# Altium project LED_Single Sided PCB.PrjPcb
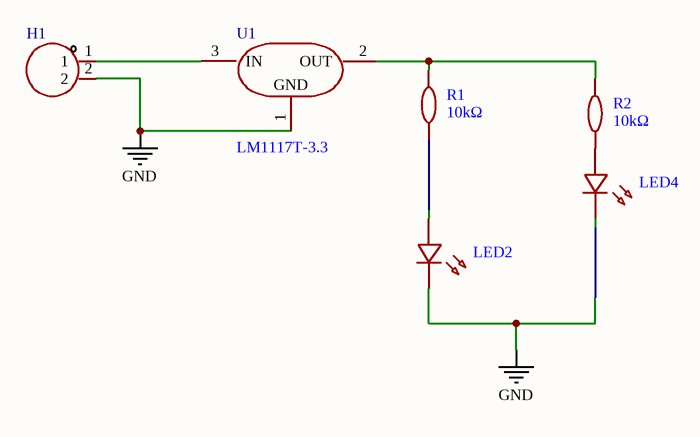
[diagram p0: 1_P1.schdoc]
1 sheet, 6 parts. Net scope: global (net labels, ports and power ports of the same name join across sheets).
Board file: PCB1.pcbdoc

## Sheet 1_P1.schdoc
size 307 x 218 mm; Symbol: Drawing-Symbol_A4; Device: Drawing-Symbol_A4; @Project Name: Single Sided; @Page Count: 1; @Update Date: 2026-02-27; @Create Date: 2026-02-27; @Schematic Name: Schematic1; @Page No: 1; @Page Name: P1; Company: EasyEDA.com; Version: V1.0; Page Size: A4; @Create Time: 07:55:02; @Update Time: 13:25:02; Width: 1170; Height: 825; Region Start: 1; X Region Count: 6; Y Region Count: 4; Blade Width: 10; Title Block Position: 3; @Board Name: Board1; SheetNumber: 1; SheetTotal: 1

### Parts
H1  (no value)  [HDR-TH_2P-P2.54-V-M-1]
LED2  (no value)  [LED-TH_BD5.8-P2.54-FD]
LED4  (no value)  [LED-TH_BD5.8-P2.54-FD]
R1  10kΩ  [RES-TH_BD1.8-L3.2-P7.20-D0.4]
R2  10kΩ  [RES-TH_BD1.8-L3.2-P7.20-D0.4]
U1  LM1117T-3.3  [TO-220-3_L10.0-W4.5-P2.54-L]

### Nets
GND: H1.2 LED2.2(A) LED4.2(A) U1.1(GND)
NetH1_1: H1.1 U1.3(IN)
NetLED2_1: LED2.1(C) R1.1
NetLED4_1: LED4.1(C) R2.1
NetR1_2: R1.2 R2.2 U1.2(OUT)

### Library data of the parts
H1 = HDR-M_2.54_1x2P: Symbol: 210S-1*2P L=11.6MMGold-plated black; Convert to PCB: yes
LED2 LED4 = LED_TH-R_5mm: Convert to PCB: yes
R1 R2 = Res_AXIAL-1/8W: Symbol: Res; Convert to PCB: yes
U1 = LM1117T-3.3: Manufacturer: HGSEMI(华冠); Add into BOM: yes; Output Type: Fixed; Voltage - Supply: 15V; Output Voltage: 3.3V; Output Current: 1A; Power Supply Rejection Ratio (PSRR): 75dB@(120Hz); Voltage Dropout: 1.25V@(1A); standby current: 10mA; Noise: 0.003%Vout; Output Configuration: Positive; Number of Outputs: 1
